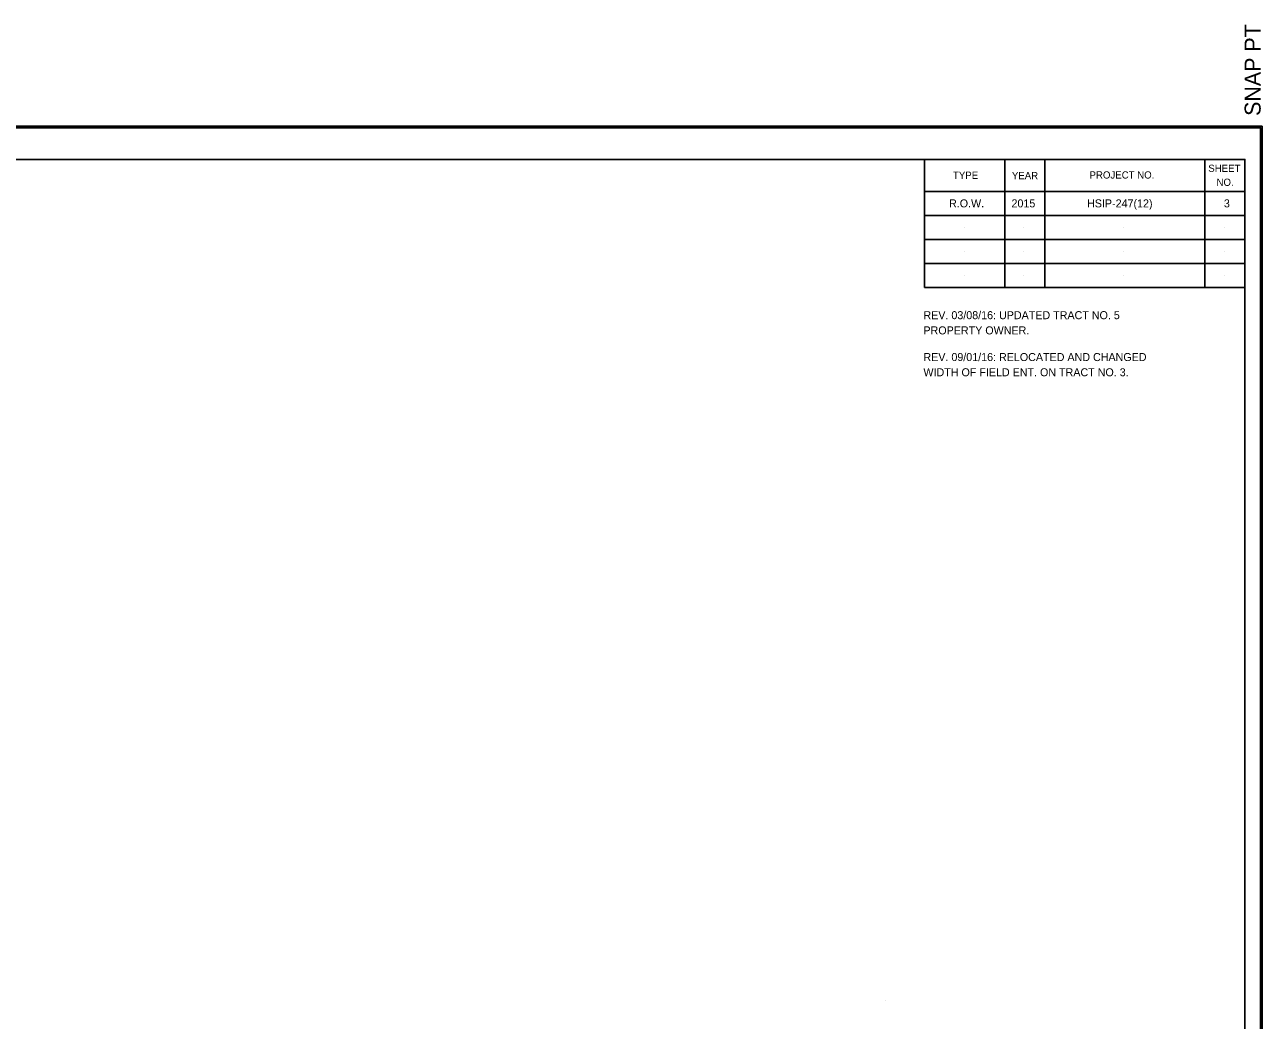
# Model space of a CAD drawing. Extents: x -200 to 1683011, y -325 to 519568.
# Drawn here: x 1681134 to 1682680, y 518325 to 519568 of the extents above; entities that cross this region are included whole.
import ezdxf

# ---------------------------------------------------------------- set-up
doc = ezdxf.new("R2010")
doc.units = 0
for name, color, linetype in [('DESIGN - SCRATCH - User 1', 7, 'Continuous'), ('DESIGN - SHEET - Corner Text', 7, 'Continuous'), ('DESIGN - SHEET - Linework', 7, 'Continuous'), ('DESIGN - SHEET - Plot Shape', 7, 'Continuous')]:
    doc.layers.add(name, color=color, linetype=linetype)

msp = doc.modelspace()

# ---------------------------------------------------------------- linework, layer by layer
at = {"layer": 'DESIGN - SCRATCH - User 1'}
for p, q in [((1682308.1, 519344.6), (1682308.1, 519344.6)), ((1682382.1, 519344.6), (1682382.1, 519344.6)), ((1682507.1, 519344.6), (1682507.1, 519344.6)), ((1682632.1, 519344.6), (1682632.1, 519344.6)), ((1682308.1, 519314.6), (1682308.1, 519314.6)), ((1682382.1, 519314.6), (1682382.1, 519314.6)), ((1682507.1, 519314.6), (1682507.1, 519314.6)), ((1682632.1, 519314.6), (1682632.1, 519314.6)), ((1682308.1, 519284.6), (1682308.1, 519284.6)), ((1682382.1, 519284.6), (1682382.1, 519284.6)), ((1682507.1, 519284.6), (1682507.1, 519284.6)), ((1682632.1, 519284.6), (1682632.1, 519284.6)), ((1682308.1, 519254.6), (1682308.1, 519254.6)), ((1682382.1, 519254.6), (1682382.1, 519254.6)), ((1682507.1, 519254.6), (1682507.1, 519254.6)), ((1682632.1, 519254.6), (1682632.1, 519254.6)), ((1682209.7, 518349.6), (1682209.7, 518349.6))]:
    msp.add_line(p, q, dxfattribs=at)
at = {"layer": 'DESIGN - SHEET - Linework'}
for p, q in [((1679275.8, 519441), (1682679.8, 519441)), ((1682679.8, 519441), (1682679.8, 517258.2))]:
    msp.add_line(p, q, dxfattribs=at)
for points in [[(1679509.7, 519399.6), (1679509.7, 517299.6), (1682658.1, 517299.6), (1682658.1, 519399.6), (1679509.7, 519399.6)], [(1682258.1, 519399.6), (1682258.1, 519239.6), (1682658.1, 519239.6), (1682658.1, 519399.6), (1682608.1, 519399.6), (1682608.1, 519239.6), (1682408.1, 519239.6), (1682408.1, 519399.6), (1682358.1, 519399.6), (1682358.1, 519239.6), (1682258.1, 519239.6), (1682258.1, 519269.6), (1682658.1, 519269.6), (1682658.1, 519299.6), (1682258.1, 519299.6), (1682258.1, 519329.6), (1682658.1, 519329.6), (1682658.1, 519359.6), (1682258.1, 519359.6)]]:
    msp.add_lwpolyline(points, dxfattribs=at)
at = {"layer": 'DESIGN - SHEET - Plot Shape'}
for points in [[(1679277.8, 519439), (1682677.8, 519439), (1682677.8, 517260.2), (1679277.8, 517260.2)], [(1679339.6, 519399.6), (1682658.1, 519399.6), (1682658.1, 517299.6), (1679339.6, 517299.6)]]:
    msp.add_lwpolyline(points, close=True, dxfattribs=at)

# ---------------------------------------------------------------- texts
at = {"layer": 'DESIGN - SHEET - Corner Text'}
for s, height, rotation, p in [('  SNAP PT', 20, 90, (1682677.8, 519439)), ('REV. 03/08/16: UPDATED TRACT NO. 5 ', 10, 360, (1682256.6, 519200)), ('PROPERTY OWNER. ', 10, 360, (1682256.6, 519181)), ('REV. 09/01/16: RELOCATED AND CHANGED', 10, 360, (1682256.6, 519147.7)), ('WIDTH OF FIELD ENT. ON TRACT NO. 3.', 10, 360, (1682256.6, 519128.7))]:
    msp.add_text(s, height=height, rotation=rotation, dxfattribs=at).set_placement(p)
for s, height, p in [('NO.', 9, (1682622.7, 519366.5)), ('R.O.W.', 10, (1682288.6, 519339.6)), ('2015', 10, (1682366.6, 519339.6)), ('HSIP-247(12)', 10, (1682461, 519339.6)), ('3', 10, (1682631.9, 519339.6))]:
    msp.add_text(s, height=height, dxfattribs=at).set_placement(p)
at = {"layer": 'DESIGN - SHEET - Linework'}
for s, p in [('TYPE', (1682293.5, 519375.2)), ('YEAR', (1682367.1, 519374.8)), ('PROJECT NO.', (1682464.1, 519375.6)), ('SHEET', (1682612.4, 519383.9)), ('NO.', (1682622.7, 519366.5))]:
    msp.add_text(s, height=9, dxfattribs=at).set_placement(p)

doc.saveas('drawing.dxf')
